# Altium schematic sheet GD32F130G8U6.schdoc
size 127 x 101 mm
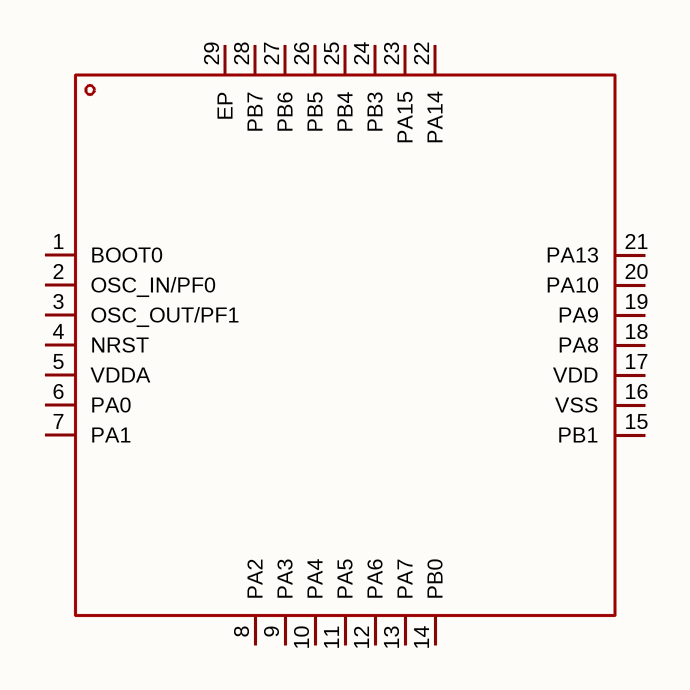
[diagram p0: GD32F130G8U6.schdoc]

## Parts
U?  gd32f130g8u6tr  [QFN-28_L4.0-W4.0-P0.40-BL-EP]  (value not drawn)

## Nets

Not connected (* = marked no-connect by the designer): U? 1(BOOT0) 2(OSC_IN/PF0) 3(OSC_OUT/PF1) 4(NRST) 5(VDDA) 6(PA0) 7(PA1) 8(PA2) 9(PA3) 10(PA4) 11(PA5) 12(PA6) 13(PA7) 14(PB0) 15(PB1) 16(VSS) 17(VDD) 18(PA8) 19(PA9) 20(PA10) 21(PA13) 22(PA14) 23(PA15) 24(PB3) 25(PB4) 26(PB5) 27(PB6) 28(PB7) 29(EP)

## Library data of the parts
U? = gd32f130g8u6tr: CPU内核:ARM Cortex-M3;CPU最大主频:72MHz;; Manufacturer: GigaDevice(兆易创新); AddInBom: yes; ModelId: 11f4b67ac5604b8a9b305e4266e81461; ModelName: QFN-28_L4.0-W4.0-H0.9-P0.40-BL-EP; ModelTransform: 157.48,157.48,0,90,0,0,0,0,0; CPU Maximum Speed: 72MHz; Program Storage Size: 64KB; Program Memory Type: FLASH; Number of I/O: 23; ADC (Bit): 12bit; Voltage - Supply: 2.6V~3.6V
